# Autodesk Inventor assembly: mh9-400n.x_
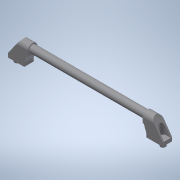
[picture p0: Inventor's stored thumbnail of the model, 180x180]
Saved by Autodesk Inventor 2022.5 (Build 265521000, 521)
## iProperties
Part Number: mh9-400n.x_
Material: 一般
Document SubType Name: Assembly
Designer: ImaoCorp
Sending System: SOLIDWORKS 2017-2017317
MC: AMD64
MC_MODEL: Intel64 Family 6 Model 60 Stepping 3, GenuineIntel
OS: Windows_NT
FRU: Parasolid Version 29.0, build 201,  4-17-2017
FORMAT: text
GUISE: transmit
KEY: mh9-400n
FILE: mh9-400n.x_t
DATE: Fri Jul 26 11:47:39 2019
Author: ImaoCorp
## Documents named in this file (4)
- X:\14_SW2022-Inv2022\00_全2023-1023新製品(TCC)まで\m\mh9-400n\MH9-400N.iam
- X:\14_SW2022-Inv2022\00_全2023-1023新製品(TCC)まで\m\mh9-400n\mh9-400n_01.ipt
- X:\14_SW2022-Inv2022\00_全2023-1023新製品(TCC)まで\m\mh9-400n\mh9-400n_02.ipt
- X:\14_SW2022-Inv2022\00_全2023-1023新製品(TCC)まで\m\mh9-400n\mh9-400n_03.ipt
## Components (3 placed, 3 different names)
1. mh9-400n_01
2. mh9-400n_02
3. mh9-400n_03
